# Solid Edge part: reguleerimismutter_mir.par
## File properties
Author: KULL
Template: Iso Metric Part.par
Last saved by: KULL
Revision: 2
Application: Solid Edge
Accuracy: 0,990
Username: KULL
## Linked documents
reguleerimismutter.par
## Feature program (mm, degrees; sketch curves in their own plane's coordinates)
part copy "CopiedPart_1"
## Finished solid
Body 1: solid body, 53 faces, 109 edges, 58 vertices.
  Faces by surface: cylinder 25, plane 13, torus 13, spline 2
  Edges by curve: circle 63, line 36, spline 6, intersection 4
Bounding box of the edges (mm; curved faces can reach further): 7.400 x 6.924 x 7.706, from (-346.16, -88.924, 49.5908) to (-338.76, -82.0002, 57.297).
Cylindrical faces by radius (mm): R0.1 x12, R0.3 x6, R1.2428 x1, R2 x2, R2.5057 x1, R3 x2, R3.7 x1
Toroidal faces (ring radius, tube radius in mm): R0.2 r0.1 x6, R0.4 r0.1 x6, R3.6 r0.1 x1
Planar faces by outward normal: oblique 13
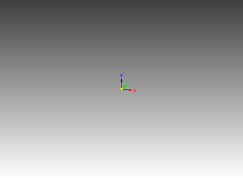
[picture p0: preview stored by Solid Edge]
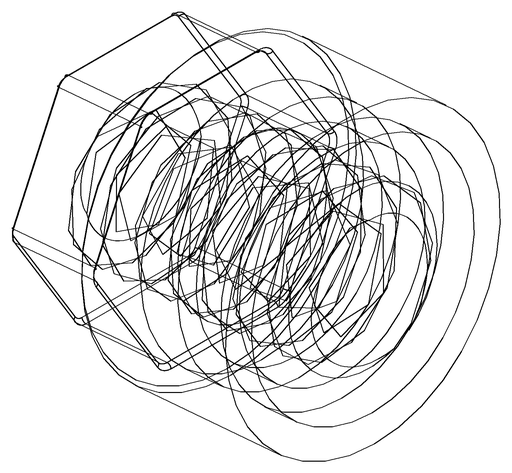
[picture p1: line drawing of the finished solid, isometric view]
